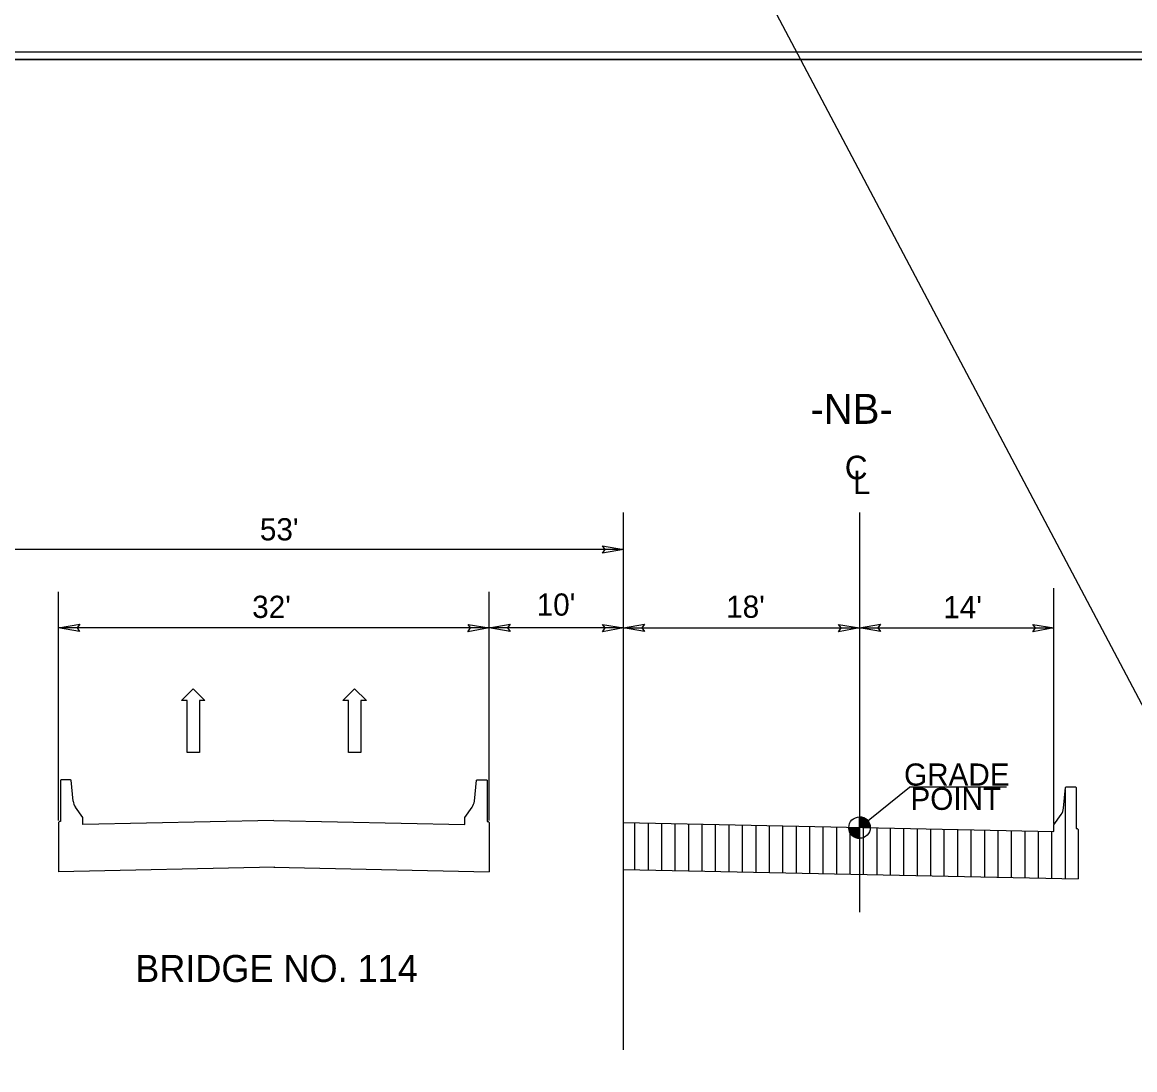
# Model space of a CAD drawing. Extents: x 2241081 to 2251104, y 658534 to 663427.
# Drawn here: x 2246330.3 to 2246702.4, y 660363.9 to 660714.3 of the extents above; entities that cross this region are included whole.
import ezdxf

# ---------------------------------------------------------------- set-up
doc = ezdxf.new("R2010")
doc.units = 0
for name, color, linetype in [('Old_Level_2', 7, 'Continuous'), ('Prop Dimension Text', 7, 'Continuous'), ('Prop Lane Arrow CELL', 7, 'Continuous'), ('Prop Roadway Bridge', 7, 'Continuous'), ('Sheet Plan CELL', 7, 'Continuous'), ('Sheet Plot Border Inside CELL', 7, 'Continuous'), ('Typical Grade Point Symbol CELL', 7, 'Continuous'), ('Typical Terminator CELL', 7, 'Continuous'), ('Typical Text Centerline CELL', 7, 'Continuous'), ('Typical Text Grade Point CELL', 7, 'Continuous')]:
    doc.layers.add(name, color=color, linetype=linetype)

msp = doc.modelspace()

# ---------------------------------------------------------------- linework, layer by layer
at = {"layer": 'Old_Level_2'}
msp.add_line((2247232.05, 659489.1), (2245149.47, 663427.07), dxfattribs=at)
at = {"layer": 'Prop Dimension Text'}
for p, q in [((2246531.42, 660446.53), (2246531.42, 660550.33)), ((2246531.42, 660537.91), (2246292.92, 660537.91)), ((2246675.42, 660446.23), (2246675.42, 660525.01)), ((2246342.42, 660447.28), (2246342.42, 660523.7)), ((2246486.42, 660447.28), (2246486.42, 660523.7)), ((2246486.42, 660511.65), (2246342.42, 660511.65)), ((2246531.42, 660511.65), (2246486.42, 660511.65)), ((2246531.42, 660511.65), (2246610.37, 660511.65)), ((2246610.37, 660511.65), (2246675.42, 660511.65)), ((2246679.24, 660427.8), (2246679.24, 660457.55)), ((2246531.42, 660370.49), (2246531.42, 660446.53)), ((2246535.24, 660430.79), (2246535.24, 660446.45)), ((2246539.74, 660430.7), (2246539.74, 660446.36)), ((2246544.24, 660430.6), (2246544.24, 660446.27)), ((2246548.74, 660430.51), (2246548.74, 660446.17)), ((2246553.24, 660430.42), (2246553.24, 660446.08)), ((2246557.74, 660430.32), (2246557.74, 660445.99)), ((2246562.24, 660430.23), (2246562.24, 660445.89)), ((2246566.74, 660430.14), (2246566.74, 660445.8)), ((2246571.24, 660430.04), (2246571.24, 660445.71)), ((2246575.74, 660429.95), (2246575.74, 660445.61)), ((2246580.24, 660429.85), (2246580.24, 660445.52)), ((2246584.74, 660429.76), (2246584.74, 660445.42)), ((2246589.24, 660429.67), (2246589.24, 660445.33)), ((2246593.74, 660429.57), (2246593.74, 660445.24)), ((2246598.24, 660429.48), (2246598.24, 660445.14)), ((2246602.74, 660429.39), (2246602.74, 660445.05)), ((2246607.24, 660429.29), (2246607.24, 660444.96)), ((2246611.74, 660429.2), (2246611.74, 660444.86)), ((2246616.24, 660429.11), (2246616.24, 660444.77)), ((2246620.74, 660429.01), (2246620.74, 660444.68)), ((2246625.24, 660428.92), (2246625.24, 660444.58)), ((2246629.74, 660428.82), (2246629.74, 660444.49)), ((2246634.24, 660428.73), (2246634.24, 660444.4)), ((2246638.74, 660428.64), (2246638.74, 660444.3)), ((2246643.24, 660428.54), (2246643.24, 660444.21)), ((2246647.74, 660428.45), (2246647.74, 660444.11)), ((2246652.24, 660428.36), (2246652.24, 660444.02)), ((2246656.74, 660428.26), (2246656.74, 660443.93)), ((2246661.24, 660428.17), (2246661.24, 660443.83)), ((2246665.74, 660428.08), (2246665.74, 660443.74)), ((2246670.24, 660427.98), (2246670.24, 660443.65)), ((2246674.74, 660427.89), (2246674.74, 660443.55))]:
    msp.add_line(p, q, dxfattribs=at)
at = {"layer": 'Prop Lane Arrow CELL'}
for p, q in [((2246383.57, 660487.35), (2246387.42, 660491.26)), ((2246387.42, 660491.26), (2246391.39, 660487.35)), ((2246437.57, 660487.35), (2246441.42, 660491.26)), ((2246441.42, 660491.26), (2246445.39, 660487.35)), ((2246385.43, 660487.35), (2246383.57, 660487.35)), ((2246385.43, 660469.99), (2246385.43, 660487.35)), ((2246391.39, 660487.35), (2246389.53, 660487.35)), ((2246389.53, 660487.35), (2246389.53, 660469.99)), ((2246439.43, 660487.35), (2246437.57, 660487.35)), ((2246439.43, 660469.99), (2246439.43, 660487.35)), ((2246445.39, 660487.35), (2246443.53, 660487.35)), ((2246443.53, 660487.35), (2246443.53, 660469.99)), ((2246389.53, 660469.99), (2246385.43, 660469.99)), ((2246443.53, 660469.99), (2246439.43, 660469.99))]:
    msp.add_line(p, q, dxfattribs=at)
at = {"layer": 'Prop Roadway Bridge'}
for p, q in [((2246343.24, 660460.9), (2246343.07, 660460.73)), ((2246343.07, 660460.73), (2246343.07, 660446.96)), ((2246346.39, 660460.9), (2246343.24, 660460.9)), ((2246346.58, 660460.71), (2246346.39, 660460.9)), ((2246347.31, 660453.74), (2246346.58, 660460.71)), ((2246481.53, 660453.74), (2246482.26, 660460.71)), ((2246482.26, 660460.71), (2246482.44, 660460.9)), ((2246482.44, 660460.9), (2246485.6, 660460.9)), ((2246485.6, 660460.9), (2246485.77, 660460.73)), ((2246485.77, 660460.73), (2246485.77, 660446.96)), ((2246678.58, 660451.33), (2246679.32, 660458.3)), ((2246679.32, 660458.3), (2246679.5, 660458.48)), ((2246679.5, 660458.48), (2246682.66, 660458.48)), ((2246682.66, 660458.48), (2246682.82, 660458.32)), ((2246682.82, 660458.32), (2246682.82, 660444.55)), ((2246350.48, 660448.27), (2246348.07, 660451.7)), ((2246478.36, 660448.27), (2246480.76, 660451.7)), ((2246342.75, 660446.96), (2246342.42, 660446.63)), ((2246342.42, 660446.63), (2246342.42, 660444.35)), ((2246343.07, 660446.96), (2246342.75, 660446.96)), ((2246350.48, 660445.95), (2246350.48, 660448.27)), ((2246414.42, 660447.28), (2246350.48, 660445.95)), ((2246414.42, 660447.28), (2246478.36, 660445.95)), ((2246478.36, 660445.95), (2246478.36, 660448.27)), ((2246485.77, 660446.96), (2246486.09, 660446.96)), ((2246486.09, 660446.96), (2246486.42, 660446.63)), ((2246486.42, 660446.63), (2246486.42, 660444.35)), ((2246531.42, 660446.53), (2246675.42, 660443.54)), ((2246675.42, 660445.85), (2246677.82, 660449.29)), ((2246342.42, 660444.35), (2246342.42, 660430.12)), ((2246486.42, 660444.35), (2246486.42, 660430.12)), ((2246675.42, 660443.54), (2246675.42, 660445.85)), ((2246682.82, 660444.55), (2246683.15, 660444.55)), ((2246683.15, 660444.55), (2246683.48, 660444.22)), ((2246683.48, 660444.22), (2246683.48, 660441.93)), ((2246683.48, 660441.93), (2246683.48, 660427.71)), ((2246414.74, 660431.62), (2246342.42, 660430.12)), ((2246414.42, 660431.62), (2246486.42, 660430.12)), ((2246531.42, 660430.87), (2246683.48, 660427.71))]:
    msp.add_line(p, q, dxfattribs=at)
for centre, start, end in [((2246351.64, 660454.2), 186.011, 214.9912), ((2246477.2, 660454.2), 325.0086, 353.9889), ((2246674.25, 660451.78), 325.0086, 353.9889)]:
    msp.add_arc(centre, 4.36, start, end, dxfattribs=at)
at = {"layer": 'Sheet Plan CELL'}
for points in [[(2245563.81, 659651.78), (2245563.79, 660701.76), (2246863.77, 660701.79), (2246863.79, 660551.73), (2247063.82, 660551.72), (2247063.82, 659651.78)], [(2247063.85, 660701.78), (2245563.81, 660701.78), (2245563.81, 659651.78), (2247063.82, 659651.78)]]:
    msp.add_lwpolyline(points, close=True, dxfattribs=at)
at = {"layer": 'Sheet Plot Border Inside CELL'}
msp.add_lwpolyline([(2245410.32, 659649.27), (2247076.31, 659649.28), (2247076.32, 660704.27), (2245410.32, 660704.27)], close=True, dxfattribs=at)
at = {"layer": 'Typical Grade Point Symbol CELL'}
for p, q in [((2246610.37, 660444.89), (2246627.06, 660458.35)), ((2246610.37, 660448.47), (2246610.37, 660444.89)), ((2246610.37, 660444.89), (2246610.37, 660448.47)), ((2246606.79, 660444.89), (2246610.37, 660444.89)), ((2246610.37, 660444.89), (2246610.37, 660441.31)), ((2246613.95, 660444.89), (2246610.37, 660444.89))]:
    msp.add_line(p, q, dxfattribs=at)
for points in [[(2246610.42, 660444.89), (2246610.42, 660448.47), (2246610.42, 660448.47)], [(2246610.49, 660444.89), (2246610.49, 660448.47)], [(2246610.57, 660444.89), (2246610.57, 660448.46)], [(2246610.64, 660444.89), (2246610.64, 660448.46)], [(2246610.71, 660444.89), (2246610.71, 660448.46)], [(2246610.78, 660444.89), (2246610.78, 660448.45)], [(2246610.85, 660444.89), (2246610.85, 660448.44)], [(2246610.92, 660444.89), (2246610.92, 660448.42)], [(2246611, 660444.89), (2246611, 660448.42)], [(2246611.07, 660444.89), (2246611.07, 660448.4)], [(2246611.14, 660444.89), (2246611.14, 660448.38)], [(2246611.21, 660444.89), (2246611.21, 660448.37)], [(2246611.28, 660444.89), (2246611.28, 660448.35)], [(2246611.35, 660444.89), (2246611.35, 660448.33)], [(2246611.42, 660444.89), (2246611.42, 660448.31)], [(2246611.5, 660444.89), (2246611.5, 660448.29)], [(2246611.57, 660444.89), (2246611.57, 660448.27)], [(2246611.64, 660444.89), (2246611.64, 660448.24)], [(2246611.71, 660444.89), (2246611.71, 660448.21)], [(2246611.78, 660444.89), (2246611.78, 660448.18)], [(2246611.85, 660444.89), (2246611.85, 660448.15)], [(2246611.93, 660444.89), (2246611.93, 660448.11)], [(2246612, 660444.89), (2246612, 660448.08)], [(2246612.07, 660444.89), (2246612.07, 660448.04)], [(2246612.14, 660444.89), (2246612.14, 660448)], [(2246612.21, 660444.89), (2246612.21, 660447.96)], [(2246612.28, 660444.89), (2246612.28, 660447.92)], [(2246612.36, 660444.89), (2246612.36, 660447.87)], [(2246612.43, 660444.89), (2246612.43, 660447.82)], [(2246612.5, 660444.89), (2246612.5, 660447.77)], [(2246612.57, 660444.89), (2246612.57, 660447.72)], [(2246612.64, 660444.89), (2246612.64, 660447.66)], [(2246612.71, 660444.89), (2246612.71, 660447.6)], [(2246612.79, 660444.89), (2246612.79, 660447.53)], [(2246612.86, 660444.89), (2246612.86, 660447.47)], [(2246612.93, 660444.89), (2246612.93, 660447.4)], [(2246613, 660444.89), (2246613, 660447.32)], [(2246613.07, 660444.89), (2246613.07, 660447.24)], [(2246613.14, 660444.89), (2246613.14, 660447.15)], [(2246613.21, 660444.89), (2246613.21, 660447.06)], [(2246613.29, 660444.89), (2246613.29, 660446.97)], [(2246613.36, 660444.89), (2246613.36, 660446.86)], [(2246613.43, 660444.89), (2246613.43, 660446.75)], [(2246613.5, 660444.89), (2246613.5, 660446.63)], [(2246613.57, 660444.89), (2246613.57, 660446.49)], [(2246606.83, 660444.38), (2246606.83, 660444.89)], [(2246606.9, 660444.02), (2246606.9, 660444.89)], [(2246606.97, 660443.77), (2246606.97, 660444.89)], [(2246607.04, 660443.57), (2246607.04, 660444.89)], [(2246607.11, 660443.4), (2246607.11, 660444.89)], [(2246607.18, 660443.25), (2246607.18, 660444.89)], [(2246607.26, 660443.12), (2246607.26, 660444.89)], [(2246607.33, 660443.01), (2246607.33, 660444.89)], [(2246607.4, 660442.89), (2246607.4, 660444.89)], [(2246607.47, 660442.79), (2246607.47, 660444.89)], [(2246607.54, 660442.7), (2246607.54, 660444.89)], [(2246607.61, 660442.61), (2246607.61, 660444.89)], [(2246607.68, 660442.52), (2246607.68, 660444.89)], [(2246607.76, 660442.44), (2246607.76, 660444.89)], [(2246607.83, 660442.37), (2246607.83, 660444.89)], [(2246607.9, 660442.3), (2246607.9, 660444.89)], [(2246607.97, 660442.23), (2246607.97, 660444.89)], [(2246608.04, 660442.17), (2246608.04, 660444.89)], [(2246608.11, 660442.11), (2246608.11, 660444.89)], [(2246608.19, 660442.05), (2246608.19, 660444.89)], [(2246608.26, 660442), (2246608.26, 660444.89)], [(2246608.33, 660441.95), (2246608.33, 660444.89)], [(2246608.4, 660441.9), (2246608.4, 660444.89)], [(2246608.47, 660441.85), (2246608.47, 660444.89)], [(2246608.54, 660441.81), (2246608.54, 660444.89)], [(2246608.62, 660441.77), (2246608.62, 660444.89)], [(2246608.69, 660441.73), (2246608.69, 660444.89)], [(2246608.76, 660441.69), (2246608.76, 660444.89)], [(2246608.83, 660441.66), (2246608.83, 660444.89)], [(2246608.9, 660441.63), (2246608.9, 660444.89)], [(2246608.97, 660441.6), (2246608.97, 660444.89)], [(2246609.05, 660441.57), (2246609.05, 660444.89)], [(2246609.12, 660441.53), (2246609.12, 660444.89)], [(2246609.19, 660441.51), (2246609.19, 660444.89)], [(2246609.26, 660441.49), (2246609.26, 660444.89)], [(2246609.33, 660441.46), (2246609.33, 660444.89)], [(2246609.4, 660441.45), (2246609.4, 660444.89)], [(2246609.47, 660441.42), (2246609.47, 660444.89)], [(2246609.55, 660441.41), (2246609.55, 660444.89)], [(2246609.62, 660441.39), (2246609.62, 660444.89)], [(2246609.69, 660441.37), (2246609.69, 660444.89)], [(2246609.76, 660441.36), (2246609.76, 660444.89)], [(2246609.83, 660441.35), (2246609.83, 660444.89)], [(2246609.9, 660441.34), (2246609.9, 660444.89)], [(2246609.98, 660441.33), (2246609.98, 660444.89)], [(2246610.05, 660441.33), (2246610.05, 660444.89)], [(2246610.12, 660441.32), (2246610.12, 660444.89)], [(2246610.19, 660441.32), (2246610.19, 660444.89)], [(2246610.26, 660441.31), (2246610.26, 660444.89)], [(2246610.33, 660441.31), (2246610.33, 660441.31), (2246610.33, 660444.89)], [(2246613.64, 660444.89), (2246613.64, 660446.34)], [(2246613.72, 660444.89), (2246613.72, 660446.17)], [(2246613.79, 660444.89), (2246613.79, 660445.96)], [(2246613.86, 660444.89), (2246613.86, 660445.7)], [(2246613.93, 660444.89), (2246613.93, 660445.28)]]:
    msp.add_lwpolyline(points, dxfattribs=at)
msp.add_circle((2246610.37, 660444.89), 3.58, dxfattribs=at)
for start, end in [(359.9905, 89.9905), (179.9905, 269.9905)]:
    msp.add_arc((2246610.37, 660444.89), 3.58, start, end, dxfattribs=at)
at = {"layer": 'Typical Terminator CELL'}
for points in [[(2246524.39, 660539.12), (2246531.42, 660537.91), (2246524.35, 660536.66), (2246525.25, 660537.91)], [(2246349.45, 660510.44), (2246342.42, 660511.65), (2246349.49, 660512.9), (2246348.59, 660511.65)], [(2246479.39, 660512.86), (2246486.42, 660511.65), (2246479.35, 660510.4), (2246480.25, 660511.65)], [(2246493.45, 660510.44), (2246486.42, 660511.65), (2246493.49, 660512.9), (2246492.59, 660511.65)], [(2246524.39, 660512.86), (2246531.42, 660511.65), (2246524.35, 660510.4), (2246525.25, 660511.65)], [(2246538.45, 660510.44), (2246531.42, 660511.65), (2246538.49, 660512.9), (2246537.59, 660511.65)], [(2246603.34, 660512.86), (2246610.37, 660511.65), (2246603.3, 660510.4), (2246604.2, 660511.65)], [(2246617.4, 660510.44), (2246610.37, 660511.65), (2246617.44, 660512.9), (2246616.54, 660511.65)], [(2246668.39, 660512.86), (2246675.42, 660511.65), (2246668.35, 660510.4), (2246669.25, 660511.65)]]:
    msp.add_lwpolyline(points, close=True, dxfattribs=at)
at = {"layer": 'Typical Text Centerline CELL'}
msp.add_line((2246610.37, 660550.33), (2246610.37, 660416.64), dxfattribs=at)
at = {"layer": 'Typical Text Grade Point CELL'}
msp.add_line((2246659.57, 660458.35), (2246627.06, 660458.35), dxfattribs=at)

# ---------------------------------------------------------------- texts
at = {"layer": 'Prop Dimension Text'}
for s, height, rotation, p in [('-NB-', 10.024, 0.0349, (2246593.95, 660579.92)), ("53'", 7.425, 359.9999, (2246409.76, 660540.95)), ("32'", 7.425, 359.9999, (2246407.19, 660515.01)), ("10'", 7.425, 359.9999, (2246502.37, 660515.77)), ("18'", 7.425, 359.9999, (2246565.76, 660515.06)), ("14'", 7.425, 359.9999, (2246638.39, 660514.92)), ('BRIDGE NO. 114', 9.0214, 359.9999, (2246368.06, 660393.23))]:
    msp.add_text(s, height=height, rotation=rotation, dxfattribs=at).set_placement(p)
at = {"layer": 'Typical Text Centerline CELL'}
for s, rotation, p in [('C', 359.9999, (2246605.45, 660561.39)), ('L', 359.9468, (2246608.17, 660556.43))]:
    msp.add_text(s, height=7.88, rotation=rotation, dxfattribs=at).set_placement(p)
at = {"layer": 'Typical Text Grade Point CELL'}
for s, p in [('GRADE', (2246625.26, 660458.9)), ('POINT', (2246627.41, 660450.8))]:
    msp.add_text(s, height=7.425, rotation=359.9999, dxfattribs=at).set_placement(p)

doc.saveas('drawing.dxf')
